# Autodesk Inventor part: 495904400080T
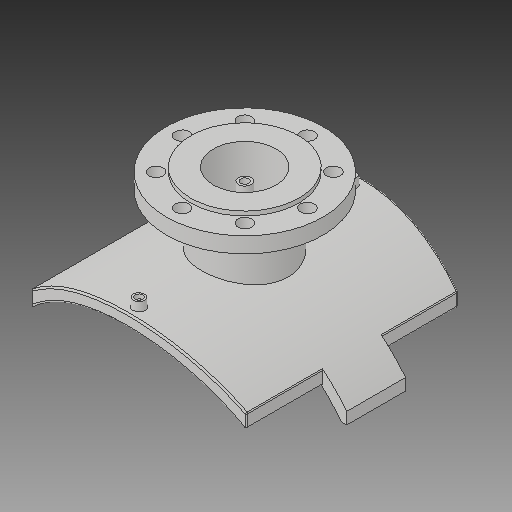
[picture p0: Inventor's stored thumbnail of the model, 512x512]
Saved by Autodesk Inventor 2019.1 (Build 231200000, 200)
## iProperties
Created: 2017-10
Part Number: 495904400080T
Material: Generic
Description: PLASSON FLANGED BRANCH SADDLE 250-400X80
Document SubType Name: Modeling
Designer: KIM
Mass: 2339.99 g
Surface Area: 3251.55 cm^2
Volume: 2339.99 cm^3
Density: 1 g/cm^3
Appearance: Default
Author: KIM
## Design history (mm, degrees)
derived "495904_495903.ipt"
feature "Solid1::495904_495903.ipt"
feature "Solid2::495904_495903.ipt"
tag "TaggingFeature1"
body "Solid1"
other parameters: "d1" = 15, "d2" = 274.5, "d4" = 0, "d6" = 75, "d7" = 0, "d12" = 225.6, "d13" = 14, "d14" = 135, "d16" = 5 deg, "d18" = 4, "d19" = 14, "d20" = 0, "d21" = 3, "d22" = 0, "d23" = 317, "d36" = 135, "d38" = 0, "d39" = 2, "d42" = 138, "d44" = 81.6, "d46" = 110.4, "d47" = 16, "d48" = 10.4, "d49" = 71.4, "d51" = 408, "d53" = 0, "d54" = 18, "d57" = 0, "d59" = 360 deg, "d63" = 0, "d66" = 102, "d67" = 15, "d68" = 51, "d70" = 0, "d71" = 2, "d72" = 305, "d_1" = 138, "B_" = 305, "H_" = 102, "x_" = 15, "D_" = 16, "s_" = 18
